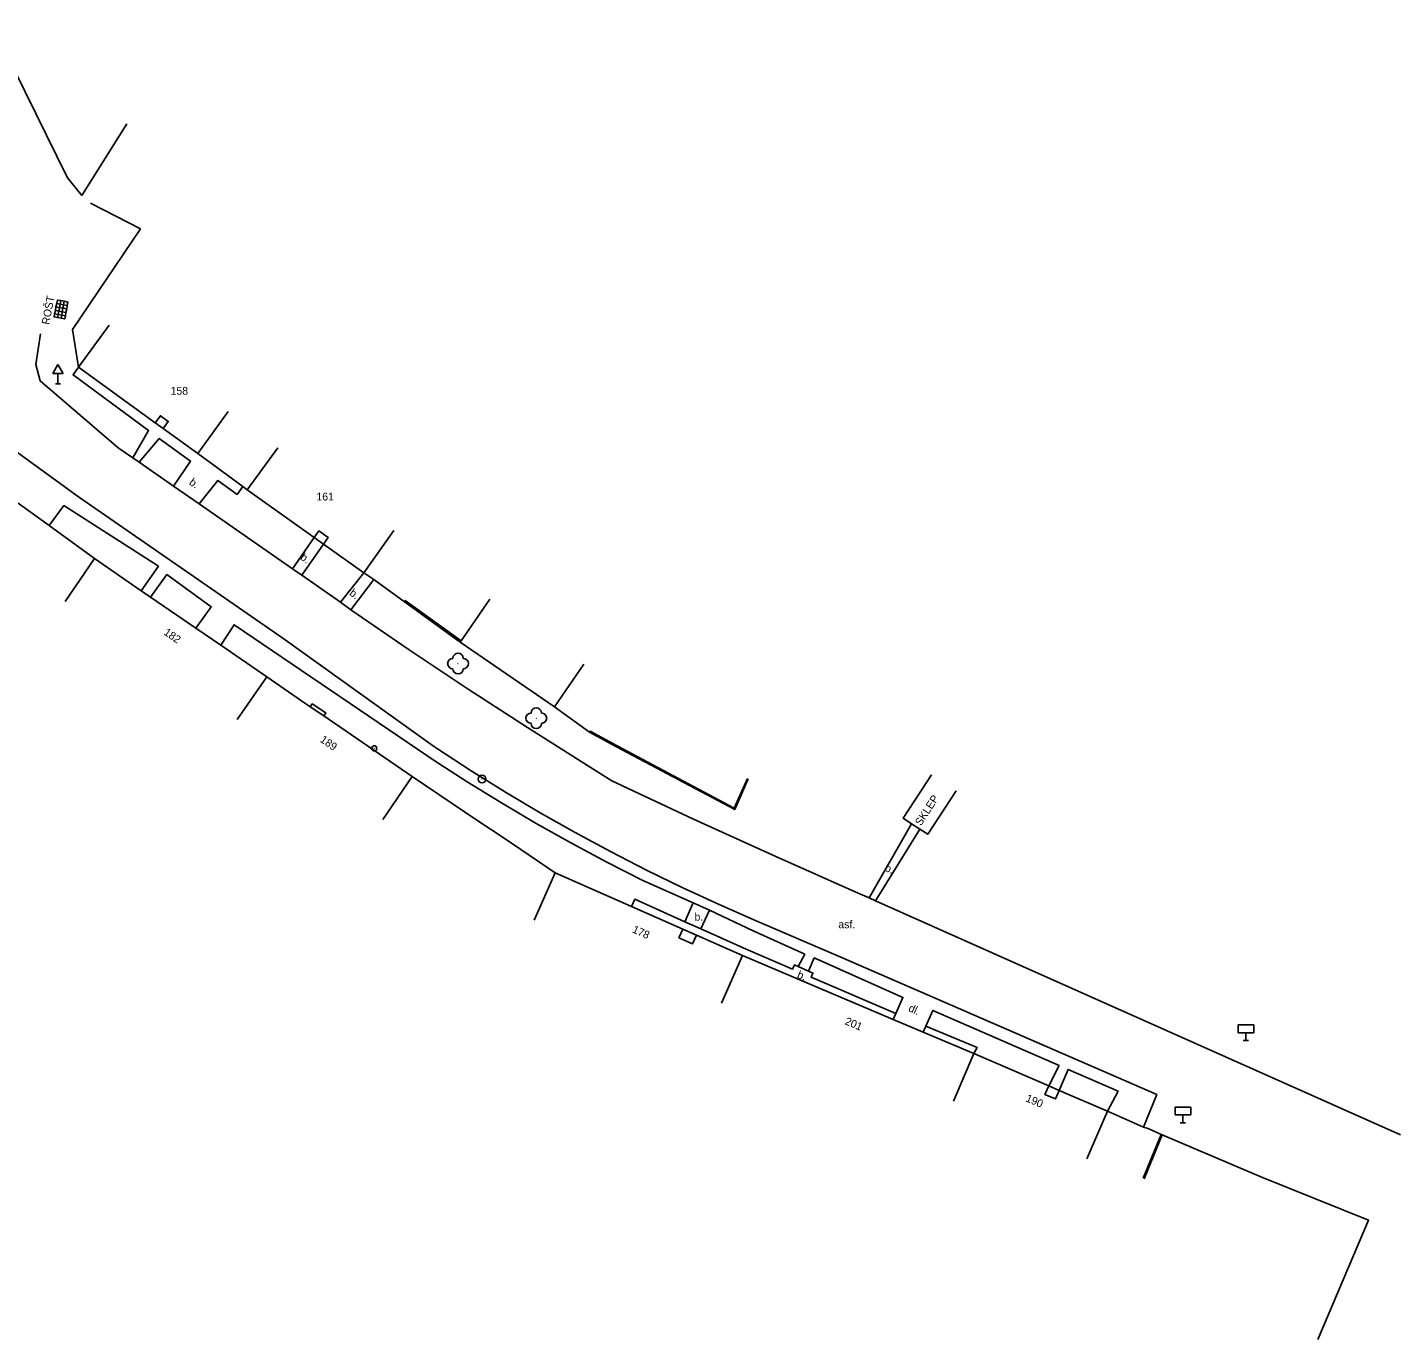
# Model space of a CAD drawing. Extents: x -582162 to -561283, y -1187583 to -1183539.
# Drawn here: x -569599.6 to -569467.5, y -1185591.1 to -1185464.9 of the extents above; entities that cross this region are included whole.
import ezdxf

# ---------------------------------------------------------------- set-up
doc = ezdxf.new("R2010")
doc.units = 0
for name, color, linetype in [('Vrstva 1', 7, 'Continuous'), ('Vrstva 10', 7, 'Continuous'), ('Vrstva 11', 7, 'Continuous'), ('Vrstva 14', 7, 'Continuous'), ('Vrstva 4', 7, 'Continuous'), ('Vrstva 5', 7, 'Continuous'), ('Vrstva 6', 7, 'Continuous'), ('Vrstva 9', 7, 'Continuous')]:
    doc.layers.add(name, color=color, linetype=linetype)

# ---------------------------------------------------------------- blocks, each defined once
blk = doc.blocks.new('1.079')
at = {"layer": 'Vrstva 1'}
for radius in [0.75, 0.001]:
    blk.add_circle((0, -0.001), radius, dxfattribs=at)
blk = doc.blocks.new('3.130')
at = {"layer": 'Vrstva 1'}
blk.add_circle((0, 0), 0.001, dxfattribs=at)
for centre, start, end in [((-1, 0), 90, 270), ((0, 1), 0, 180), ((1, 0), 270, 90), ((0, -1), 180, 360)]:
    blk.add_arc(centre, 1, start, end, dxfattribs=at)
blk = doc.blocks.new('4.110')
at = {"layer": 'Vrstva 1'}
for radius in [0.5, 0.001]:
    blk.add_circle((-0.001, 0), radius, dxfattribs=at)
blk = doc.blocks.new('5.261')
at = {"layer": 'Vrstva 1'}
for p, q in [((-0.5, 0), (0.5, 0)), ((0, 1.5), (0, 0))]:
    blk.add_line(p, q, dxfattribs=at)
blk.add_lwpolyline([(-1.5, 1.5), (1.5, 1.5), (1.5, 3), (-1.5, 3)], close=True, dxfattribs=at)
blk = doc.blocks.new('5.270')
at = {"layer": 'Vrstva 1'}
for p, q in [((0, 3.732), (-1, 2)), ((0, 3.732), (1, 2)), ((-1, 2), (1, 2)), ((-0.5, 0), (0.5, 0)), ((0, 0), (0, 2))]:
    blk.add_line(p, q, dxfattribs=at)

msp = doc.modelspace()

# ---------------------------------------------------------------- linework, layer by layer
at = {"layer": 'Vrstva 10'}
for points in [[(-569635.96, -1185480.06), (-569594.68, -1185510.02), (-569575.05, -1185523.63), (-569560.53, -1185534.03), (-569560.16, -1185534.28), (-569556.91, -1185536.4), (-569553.62, -1185538.44), (-569550.28, -1185540.42), (-569546.91, -1185542.33), (-569543.5, -1185544.17), (-569540.05, -1185545.94), (-569536.56, -1185547.64), (-569533.04, -1185549.27), (-569529.49, -1185550.82), (-569521.35, -1185554.32)], [(-569596.92, -1185492.09), (-569596.86, -1185491.76)], [(-569596.86, -1185491.76), (-569596.79, -1185491.42)], [(-569596.86, -1185491.76), (-569596.52, -1185491.82)], [(-569596.79, -1185491.42), (-569596.73, -1185491.09), (-569596.4, -1185491.15)], [(-569596.79, -1185491.42), (-569596.46, -1185491.48)], [(-569596.52, -1185491.82), (-569596.46, -1185491.48)], [(-569596.46, -1185491.48), (-569596.4, -1185491.15)], [(-569596.46, -1185491.48), (-569596.13, -1185491.55)], [(-569596.4, -1185491.15), (-569596.06, -1185491.21)], [(-569596.19, -1185491.88), (-569596.13, -1185491.55)], [(-569596.13, -1185491.55), (-569596.06, -1185491.21)], [(-569596.13, -1185491.55), (-569595.77, -1185491.62)], [(-569596.06, -1185491.21), (-569595.71, -1185491.28), (-569595.77, -1185491.62)], [(-569595.77, -1185491.62), (-569595.83, -1185491.95)], [(-569596.7, -1185492.78), (-569597.04, -1185492.72), (-569596.99, -1185492.43)], [(-569596.99, -1185492.43), (-569596.92, -1185492.09)], [(-569596.99, -1185492.43), (-569596.65, -1185492.49)], [(-569596.92, -1185492.09), (-569596.58, -1185492.15)], [(-569596.7, -1185492.78), (-569596.65, -1185492.49)], [(-569596.37, -1185492.84), (-569596.7, -1185492.78)], [(-569596.65, -1185492.49), (-569596.58, -1185492.15)], [(-569596.65, -1185492.49), (-569596.31, -1185492.55)], [(-569596.58, -1185492.15), (-569596.52, -1185491.82)], [(-569596.58, -1185492.15), (-569596.25, -1185492.21)], [(-569596.52, -1185491.82), (-569596.19, -1185491.88)], [(-569596.37, -1185492.84), (-569596.31, -1185492.55)], [(-569595.96, -1185492.62), (-569596.02, -1185492.91), (-569596.37, -1185492.84)], [(-569596.31, -1185492.55), (-569596.25, -1185492.21)], [(-569596.31, -1185492.55), (-569595.96, -1185492.62)], [(-569596.25, -1185492.21), (-569596.19, -1185491.88)], [(-569596.25, -1185492.21), (-569595.9, -1185492.28)], [(-569596.19, -1185491.88), (-569595.83, -1185491.95)], [(-569595.9, -1185492.28), (-569595.96, -1185492.62)], [(-569595.83, -1185491.95), (-569595.9, -1185492.28)], [(-569598.36, -1185494.34), (-569598.8, -1185497.3), (-569598.39, -1185498.88)], [(-569594.69, -1185497.55), (-569595.21, -1185498.3), (-569587.95, -1185503.65), (-569589.47, -1185506.28)], [(-569598.39, -1185498.88), (-569590.87, -1185505.31)], [(-569588.87, -1185506.7), (-569586.92, -1185504.4), (-569583.93, -1185506.58), (-569585.55, -1185509)], [(-569590.87, -1185505.31), (-569589.47, -1185506.28)], [(-569589.47, -1185506.28), (-569588.87, -1185506.7)], [(-569588.87, -1185506.7), (-569585.55, -1185509)], [(-569583.09, -1185510.71), (-569581.3, -1185508.47), (-569579.43, -1185509.8), (-569578.89, -1185509.04)], [(-569585.55, -1185509), (-569583.09, -1185510.71)], [(-569597.53, -1185512.8), (-569596.1, -1185510.87), (-569587.01, -1185516.71), (-569588.66, -1185519.06)], [(-569583.09, -1185510.71), (-569574.12, -1185516.94)], [(-569572.01, -1185513.95), (-569574.12, -1185516.94)], [(-569571.12, -1185514.58), (-569573.22, -1185517.56)], [(-569587.76, -1185519.68), (-569586.18, -1185517.51), (-569581.94, -1185520.61), (-569583.42, -1185522.66)], [(-569574.12, -1185516.94), (-569573.22, -1185517.56)], [(-569573.22, -1185517.56), (-569569.49, -1185520.15)], [(-569567.24, -1185517.35), (-569569.49, -1185520.15)], [(-569568.5, -1185520.9), (-569566.27, -1185517.97)], [(-569569.49, -1185520.15), (-569568.5, -1185520.9)], [(-569568.5, -1185520.9), (-569562.88, -1185524.75), (-569557.2, -1185528.53), (-569551.49, -1185532.24), (-569545.73, -1185535.89), (-569543.39, -1185537.35), (-569535.52, -1185541.03), (-569527.61, -1185544.64), (-569519.67, -1185548.18), (-569518.63, -1185548.63)], [(-569540.39, -1185546.94), (-569543.85, -1185545.18), (-569547.27, -1185543.35), (-569550.66, -1185541.45), (-569554, -1185539.48), (-569557.3, -1185537.44), (-569560.56, -1185535.34), (-569561.19, -1185534.92), (-569579.73, -1185522.34), (-569581.01, -1185524.31)], [(-569572.39, -1185530.22), (-569572.21, -1185529.95), (-569570.9, -1185530.81), (-569571.1, -1185531.11)], [(-569514.55, -1185541.48), (-569518.63, -1185548.63)], [(-569518.01, -1185548.89), (-569513.76, -1185542)], [(-569529.8, -1185551.78), (-569533.98, -1185549.81), (-569535.56, -1185549.09), (-569540.39, -1185546.94)], [(-569541.49, -1185549.45), (-569541.17, -1185548.75), (-569536.37, -1185550.91), (-569534.82, -1185551.61), (-569530.47, -1185553.57), (-569526, -1185555.49), (-569525.82, -1185555.07), (-569525.45, -1185555.23)], [(-569536.37, -1185550.91), (-569535.56, -1185549.09)], [(-569534.82, -1185551.61), (-569533.98, -1185549.81)], [(-569518.63, -1185548.63), (-569518.01, -1185548.89)], [(-569518.01, -1185548.89), (-569467.5, -1185571.42)], [(-569525.45, -1185555.23), (-569524.82, -1185554.05), (-569529.8, -1185551.78)], [(-569524.47, -1185555.66), (-569523.9, -1185554.4), (-569515.37, -1185558.2), (-569516.06, -1185559.75)], [(-569521.35, -1185554.32), (-569490.94, -1185567.53)], [(-569525.45, -1185555.23), (-569524.47, -1185555.66)], [(-569516.06, -1185559.75), (-569524.2, -1185556.26), (-569524.03, -1185555.85), (-569524.47, -1185555.66)], [(-569516.3, -1185560.31), (-569516.06, -1185559.75)], [(-569513.18, -1185560.97), (-569512.49, -1185559.45), (-569500.35, -1185564.76), (-569501.35, -1185566.7)], [(-569513.43, -1185561.53), (-569513.18, -1185560.97)], [(-569513.18, -1185560.97), (-569508.24, -1185563.01), (-569508.56, -1185563.59)], [(-569500.34, -1185567.14), (-569499.48, -1185565.13), (-569494.68, -1185567.22)], [(-569494.68, -1185567.22), (-569495.7, -1185569.14)], [(-569490.94, -1185567.53), (-569492.23, -1185570.68)]]:
    msp.add_lwpolyline(points, dxfattribs=at)
at = {"layer": 'Vrstva 4'}
for points in [[(-569594.69, -1185497.55), (-569591.75, -1185493.51)], [(-569587.32, -1185502.91), (-569594.69, -1185497.55)], [(-569586.56, -1185503.46), (-569586.06, -1185502.77), (-569586.82, -1185502.22), (-569587.32, -1185502.91)], [(-569586.56, -1185503.46), (-569587.32, -1185502.91)], [(-569583.2, -1185505.87), (-569586.56, -1185503.46)], [(-569575.53, -1185505.3), (-569578.47, -1185509.34)], [(-569601.96, -1185509.58), (-569597.53, -1185512.8)], [(-569578.47, -1185509.34), (-569578.89, -1185509.04)], [(-569578.47, -1185509.34), (-569572.01, -1185513.95)], [(-569597.53, -1185512.8), (-569593.16, -1185515.97)], [(-569572.01, -1185513.95), (-569571.56, -1185513.31), (-569570.67, -1185513.95), (-569571.12, -1185514.58)], [(-569572.01, -1185513.95), (-569571.12, -1185514.58)], [(-569567.24, -1185517.35), (-569564.34, -1185513.28)], [(-569571.12, -1185514.58), (-569567.24, -1185517.35)], [(-569595.99, -1185520.09), (-569593.16, -1185515.97)], [(-569593.16, -1185515.97), (-569588.66, -1185519.06)], [(-569588.66, -1185519.06), (-569587.76, -1185519.68)], [(-569587.76, -1185519.68), (-569583.42, -1185522.66)], [(-569555.13, -1185519.89), (-569557.88, -1185523.89)], [(-569583.42, -1185522.66), (-569581.01, -1185524.31)], [(-569581.01, -1185524.31), (-569576.59, -1185527.34)], [(-569557.88, -1185523.89), (-569557.96, -1185524.01)], [(-569557.96, -1185524.01), (-569548.89, -1185530.24)], [(-569548.89, -1185530.24), (-569546.06, -1185526.12)], [(-569579.42, -1185531.46), (-569576.59, -1185527.34)], [(-569576.59, -1185527.34), (-569572.39, -1185530.22)], [(-569572.39, -1185530.22), (-569571.1, -1185531.11)], [(-569571.1, -1185531.11), (-569562.58, -1185536.95)], [(-569562.58, -1185536.95), (-569565.41, -1185541.07)], [(-569512.63, -1185536.77), (-569515.35, -1185540.96), (-569514.55, -1185541.48)], [(-569513.76, -1185542), (-569512.98, -1185542.5), (-569510.26, -1185538.31)], [(-569514.55, -1185541.48), (-569513.76, -1185542)], [(-569550.85, -1185550.78), (-569548.83, -1185546.21)], [(-569548.83, -1185546.21), (-569541.49, -1185549.45)], [(-569541.49, -1185549.45), (-569536.56, -1185551.63)], [(-569535.25, -1185552.21), (-569535.61, -1185553.03), (-569536.93, -1185552.45), (-569536.56, -1185551.63)], [(-569536.56, -1185551.63), (-569535.25, -1185552.21)], [(-569535.25, -1185552.21), (-569530.81, -1185554.17)], [(-569532.83, -1185558.74), (-569530.81, -1185554.17)], [(-569530.81, -1185554.17), (-569516.3, -1185560.31)], [(-569516.3, -1185560.31), (-569513.43, -1185561.53)], [(-569513.43, -1185561.53), (-569508.56, -1185563.59)], [(-569510.51, -1185568.19), (-569508.56, -1185563.59)], [(-569508.56, -1185563.59), (-569501.35, -1185566.7)], [(-569500.34, -1185567.14), (-569500.69, -1185567.96), (-569501.71, -1185567.53), (-569501.35, -1185566.7)], [(-569501.35, -1185566.7), (-569500.34, -1185567.14)], [(-569500.34, -1185567.14), (-569495.7, -1185569.14)], [(-569495.7, -1185569.14), (-569497.68, -1185573.73)]]:
    msp.add_lwpolyline(points, dxfattribs=at)
at = {"layer": 'Vrstva 5'}
msp.add_lwpolyline([(-569580.29, -1185501.81), (-569583.2, -1185505.87)], dxfattribs=at)
at = {"layer": 'Vrstva 9'}
for points in [[(-569595.74, -1185479.34), (-569602.89, -1185464.86)], [(-569594.38, -1185481.04), (-569590.06, -1185474.12)], [(-569595.74, -1185479.34), (-569594.38, -1185481.04)], [(-569594.69, -1185497.55), (-569595.26, -1185493.91), (-569588.73, -1185484.24), (-569593.54, -1185481.76)], [(-569583.2, -1185505.87), (-569578.89, -1185509.04)], [(-569567.24, -1185517.35), (-569566.27, -1185517.97)], [(-569566.27, -1185517.97), (-569563.34, -1185520.13)], [(-569563.34, -1185520.13), (-569563.25, -1185520.01), (-569557.88, -1185523.89)], [(-569557.96, -1185524.01), (-569563.34, -1185520.13)], [(-569545.52, -1185532.68), (-569548.89, -1185530.24)], [(-569545.52, -1185532.68), (-569545.47, -1185532.59), (-569542.87, -1185533.99)], [(-569542.92, -1185534.08), (-569545.52, -1185532.68)], [(-569542.92, -1185534.08), (-569542.87, -1185533.99)], [(-569530.34, -1185537.12), (-569531.6, -1185539.99), (-569542.87, -1185533.99)], [(-569530.25, -1185537.16), (-569531.55, -1185540.13), (-569542.92, -1185534.08)], [(-569562.58, -1185536.95), (-569556.28, -1185541.2)], [(-569553.85, -1185542.82), (-569556.28, -1185541.2)], [(-569553.85, -1185542.82), (-569548.83, -1185546.21)], [(-569491.77, -1185570.81), (-569492.23, -1185570.68), (-569495.7, -1185569.14)], [(-569491.77, -1185570.81), (-569490.53, -1185571.38)], [(-569490.53, -1185571.38), (-569492.26, -1185575.6)], [(-569490.44, -1185571.42), (-569492.16, -1185575.64)], [(-569490.44, -1185571.42), (-569490.53, -1185571.38)], [(-569490.44, -1185571.42), (-569483.96, -1185574.19)], [(-569480.79, -1185575.54), (-569483.96, -1185574.19)], [(-569480.79, -1185575.54), (-569470.59, -1185579.62), (-569475.47, -1185591.12)]]:
    msp.add_lwpolyline(points, dxfattribs=at)

# ---------------------------------------------------------------- block references
at = {"layer": 'Vrstva 1', "xscale": 0.5, "yscale": 0.5}
msp.add_blockref('1.079', (-569555.87, -1185537.18), dxfattribs=at)
at = {"layer": 'Vrstva 11', "xscale": 0.5, "yscale": 0.5}
for p in [(-569558.18, -1185526.07), (-569550.65, -1185531.33)]:
    msp.add_blockref('3.130', p, dxfattribs=at)
at = {"layer": 'Vrstva 9', "xscale": 0.5, "yscale": 0.5}
for name, p in [('5.270', (-569596.67, -1185499.16)), ('4.110', (-569566.24, -1185534.23)), ('5.261', (-569482.38, -1185562.35)), ('5.261', (-569488.44, -1185570.26))]:
    msp.add_blockref(name, p, dxfattribs=at)

# ---------------------------------------------------------------- texts
at = {"layer": 'Vrstva 14'}
for s, rotation, p in [('ROŠT', 79.372, (-569597.51, -1185493.5)), ('b.', 324.501, (-569584.11, -1185508.78)), ('b.', 324.501, (-569573.42, -1185515.99)), ('b.', 324.501, (-569568.69, -1185519.43)), ('SKLEP', 56.99, (-569513.64, -1185541.74)), ('b.', 335.961, (-569517.19, -1185546)), ('b.', 337.054, (-569525.62, -1185556.28)), ('dl.', 335.495, (-569514.91, -1185559.48))]:
    msp.add_text(s, height=0.75, rotation=rotation, dxfattribs=at).set_placement(p)
for s, p in [('b.', (-569535.43, -1185550.81)), ('asf.', (-569521.59, -1185551.54))]:
    msp.add_text(s, height=0.75, dxfattribs=at).set_placement(p)
at = {"layer": 'Vrstva 6'}
for s, p in [('158', (-569585.83, -1185500.2)), ('161', (-569571.8, -1185510.38))]:
    msp.add_text(s, height=0.75, dxfattribs=at).set_placement(p)
for s, rotation, p in [('182', 325.543, (-569586.56, -1185523.23)), ('189', 325.552, (-569571.52, -1185533.55)), ('178', 336.167, (-569541.48, -1185551.92)), ('201', 337.054, (-569521.02, -1185560.76)), ('190', 336.656, (-569503.63, -1185568.17))]:
    msp.add_text(s, height=0.75, rotation=rotation, dxfattribs=at).set_placement(p)

doc.saveas('drawing.dxf')
